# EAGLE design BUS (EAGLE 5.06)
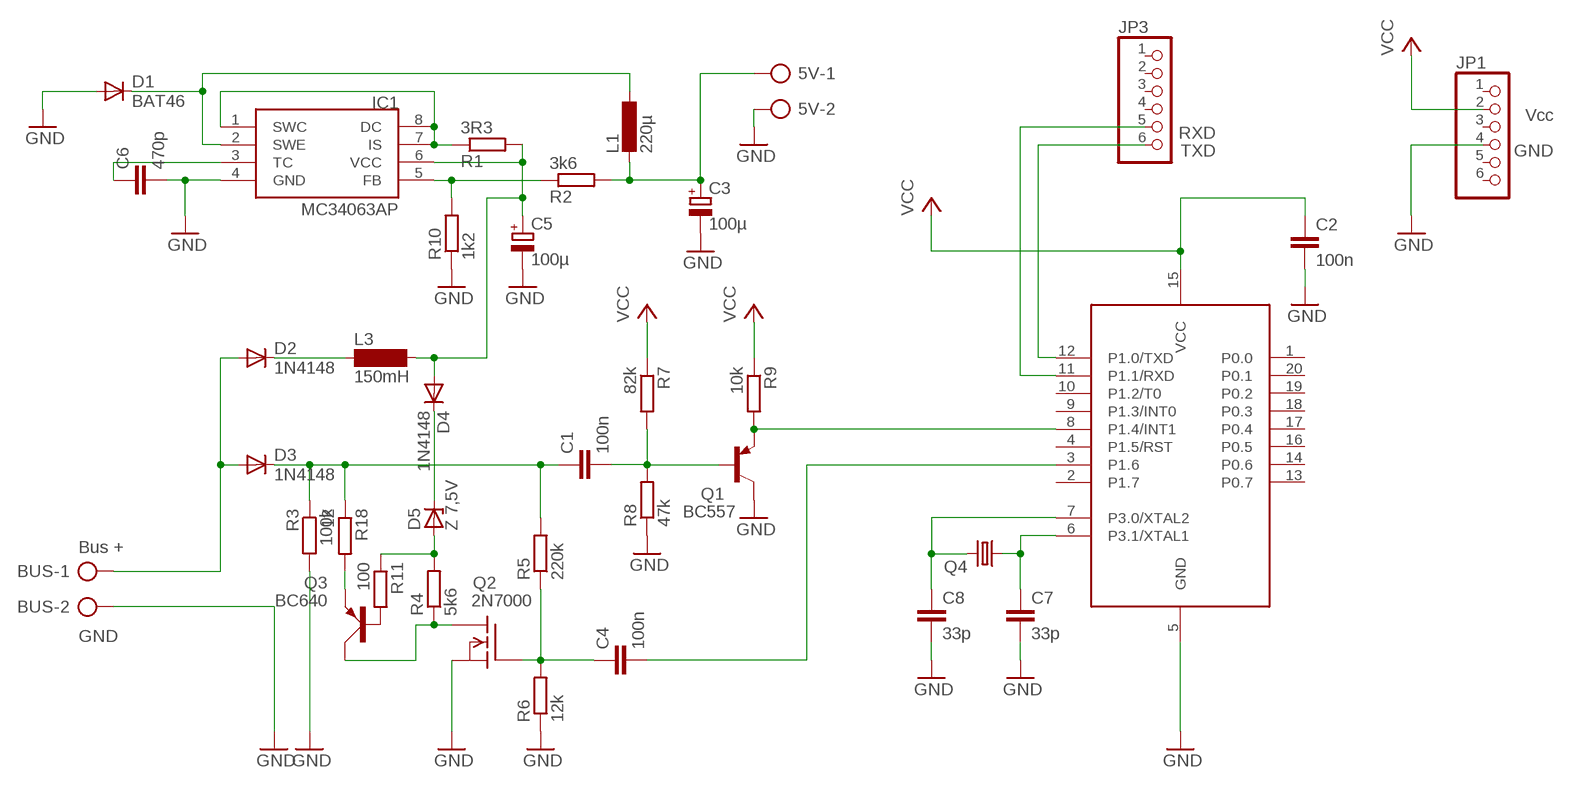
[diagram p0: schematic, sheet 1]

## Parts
5V  AK300/2  [AK300/2]
BUS  AK300/2  [AK300/2]
C1  100n  C-EU050-024X044  [C050-024X044]
C2  100n  C-EU050-024X044  [C050-024X044]
C3  100µ  CPOL-EUE5-8.5  [E5-8,5]
C4  100n  C-EU050-024X044  [C050-024X044]
C5  100µ  CPOL-EUE5-8.5  [E5-8,5]
C6  470p  C-EU025-024X044  [C025-024X044]
C7  33p  C-EU025-024X044  [C025-024X044]
C8  33p  C-EU025-024X044  [C025-024X044]
D1  BAT46  1N4148DO35-7  [DO35-7]
D2  1N4148  1N4148DO35-7  [DO35-7]
D3  1N4148  1N4148DO35-7  [DO35-7]
D4  1N4148  1N4148DO35-7  [DO35-7]
D5  Z 7,5V  ZENER-DIODEZD-7.5  [ZDIO-7.5]
IC1  MC34063AP  [DIL08]
JP1  PINHD-1X6  [1X06]
JP3  PINHD-1X6  [1X06]
L1  220µ  L-EU2200-12.7  [2200-12.7]
L3  150mH  SD12-1000  [SD12_1000]
Q1  BC557  [TO92]
Q2  2N7000  VN2222KM  [TO237]
Q3  BC640  [SOT54D]
Q4  CRYSTALHC49S  [HC49/S]
R1  3R3  R-EU_0207/10  [0207/10]
R2  3k6  R-EU_0207/10  [0207/10]
R3  100k  R-EU_0207/10  [0207/10]
R4  5k6  R-EU_0207/10  [0207/10]
R5  220k  R-EU_0207/10  [0207/10]
R6  12k  R-EU_0207/10  [0207/10]
R7  82k  R-EU_0207/10  [0207/10]
R8  47k  R-EU_0207/10  [0207/10]
R9  10k  R-EU_0207/10  [0207/10]
R10  1k2  R-EU_0207/10  [0207/10]
R11  100  R-EU_0207/10  [0207/10]
R18  12  R-EU_0207/10  [0207/10]
U1  89LPC922  [DIL20]

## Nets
EIB+: BUS.1 D2.A D3.A
GND: 5V.2 BUS.2 C2.2 C3.- C5.- C6.2 C7.2 C8.2 D1.A IC1.4(GND) JP1.4 Q1.3(C) Q2.3(S) R3.2 R6.1 R8.1 R10.1 U1.5(GND)
N$1: Q1.1(E) R9.2 U1.8(P1.4/INT1)
N$2: C1.2 Q1.2(B) R7.2 R8.2
N$3: C8.1 Q4.2 U1.7(P3.0/XTAL2)
N$4: C1.1 D3.C R3.1 R5.2 R18.1
N$5: C4.2 U1.3(P1.6)
N$7: C5.+ D4.A IC1.6(VCC) L3.2 R1.2
N$8: IC1.1(SWC) IC1.7(IS) IC1.8(DC) R1.1
N$9: 5V.1 C3.+ L1.2 R2.2
N$10: JP3.6 U1.12(P1.0/TXD)
N$11: IC1.5(FB) R2.1 R10.2
N$12: D1.C IC1.2(SWE) L1.1
N$13: D2.C L3.1
N$14: C6.1 IC1.3(TC)
N$15: D4.C D5.C
N$16: JP3.5 U1.11(P1.1/RXD)
N$17: C7.1 Q4.1 U1.6(P3.1/XTAL1)
N$25: D5.A R4.2 R11.1
N$26: Q2.1(D) Q3.C R4.1
N$28: Q3.B R11.2
N$33: Q3.E R18.2
N$34: C4.1 Q2.2(G) R5.1 R6.2
VCC: C2.1 JP1.2 R7.1 R9.1 U1.15(VCC)
Unconnected: JP1.1 JP1.3 JP1.5 JP1.6 JP3.1 JP3.2 JP3.3 JP3.4 U1.1(P0.0) U1.2(P1.7) U1.4(P1.5/RST) U1.9(P1.3/INT0) U1.10(P1.2/T0) U1.13(P0.7) U1.14(P0.6) U1.16(P0.5) U1.17(P0.4) U1.18(P0.3) U1.19(P0.2) U1.20(P0.1)

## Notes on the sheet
- Vcc
- RXD
- TXD | GND
- Bus +
- GND

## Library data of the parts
5V BUS = con-ptr500:AK300/2: CONNECTOR
C1 C2 C4 C6-C8 = rcl:C-EU: CAPACITOR, European symbol
C3 C5 = rcl:CPOL-EU: POLARIZED CAPACITOR, European symbol
D1-D4 = diode:1N4148: DIODE
D5 = diode:ZENER-DIODE: Z-Diode
IC1 = mc34063:MC34063
JP1 JP3 = pinhead:PINHD-1X6: PIN HEADER
L1 = rcl:L-EU: INDUCTOR, European symbol
L3 = inductor-neosid:SD12: INDUCTOR
Q1 = transistor-pnp:BC557: PNP Transistor
Q2 = transistor-fet:VN2222KM: N-Channel Enhancement MOSFET (VMOS); 60V; 0,5A; 7,5Ohm
Q3 = transistor-small-signal:BC640: PNP TRANSISTOR
Q4 = crystal:CRYSTAL: CRYSTAL
R1-R11 R18 = resistor:R-EU_: RESISTOR, European symbol
U1 = micro-philips:89LPC922

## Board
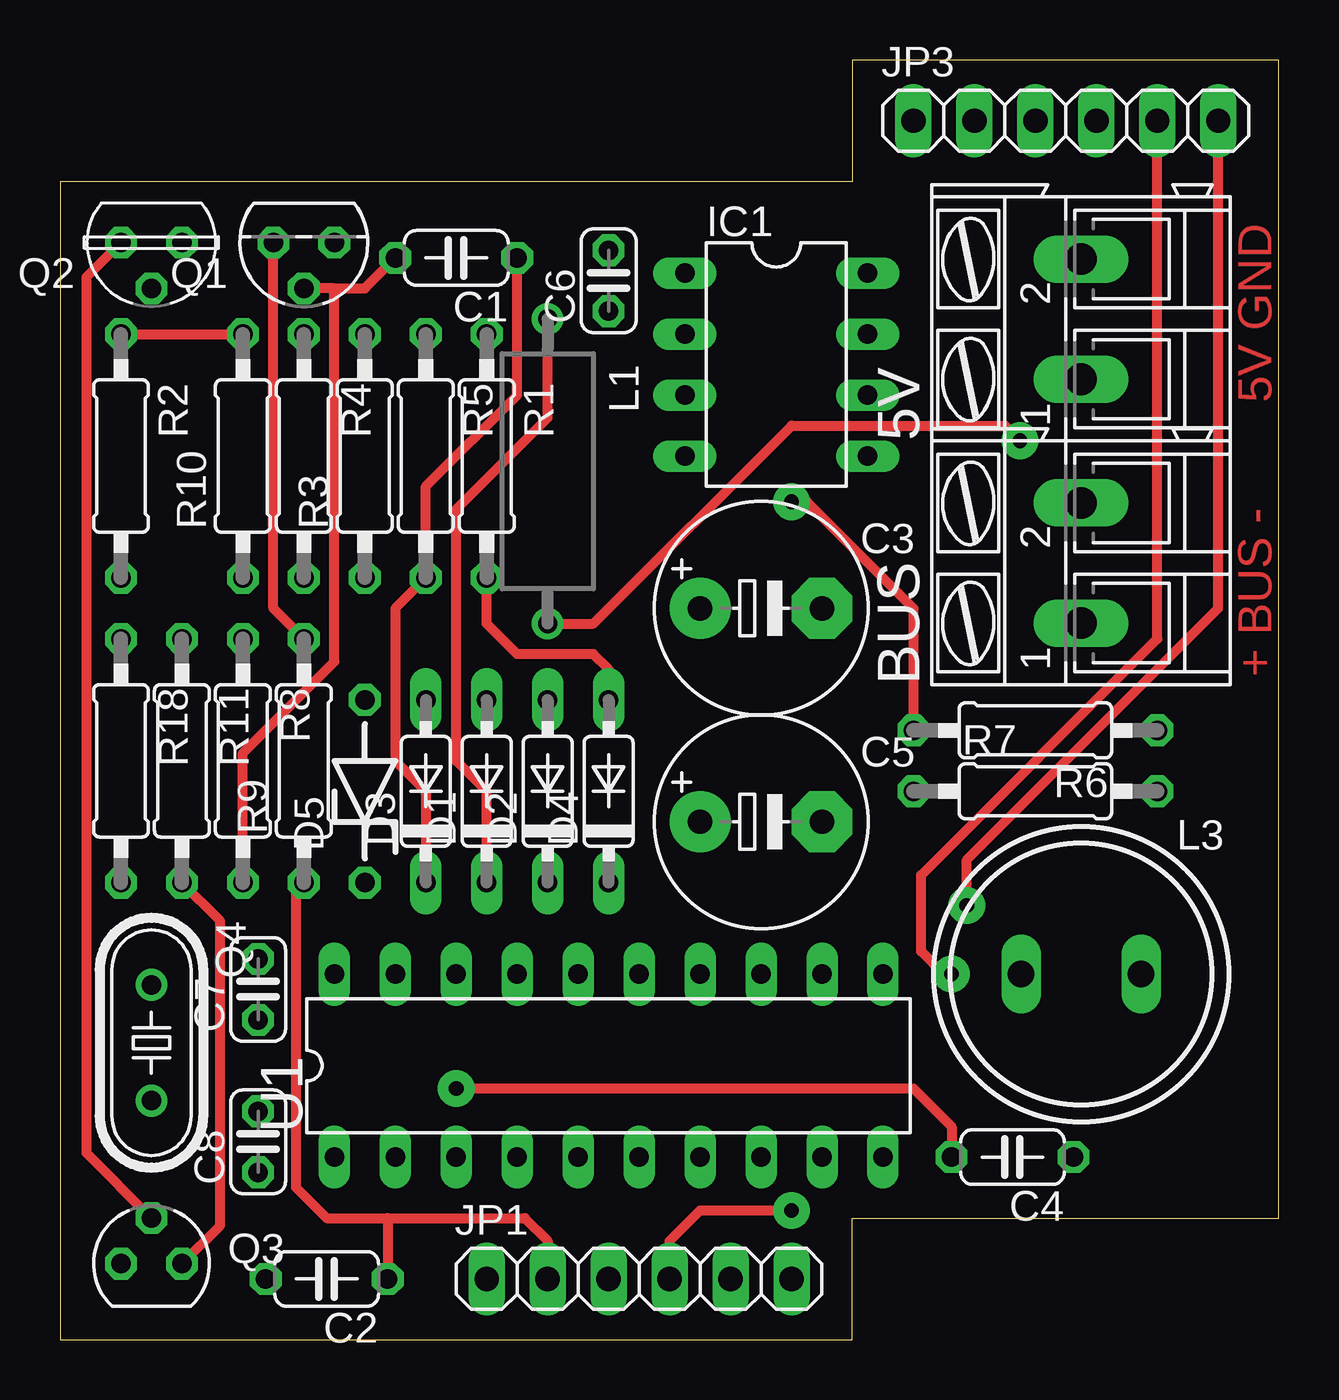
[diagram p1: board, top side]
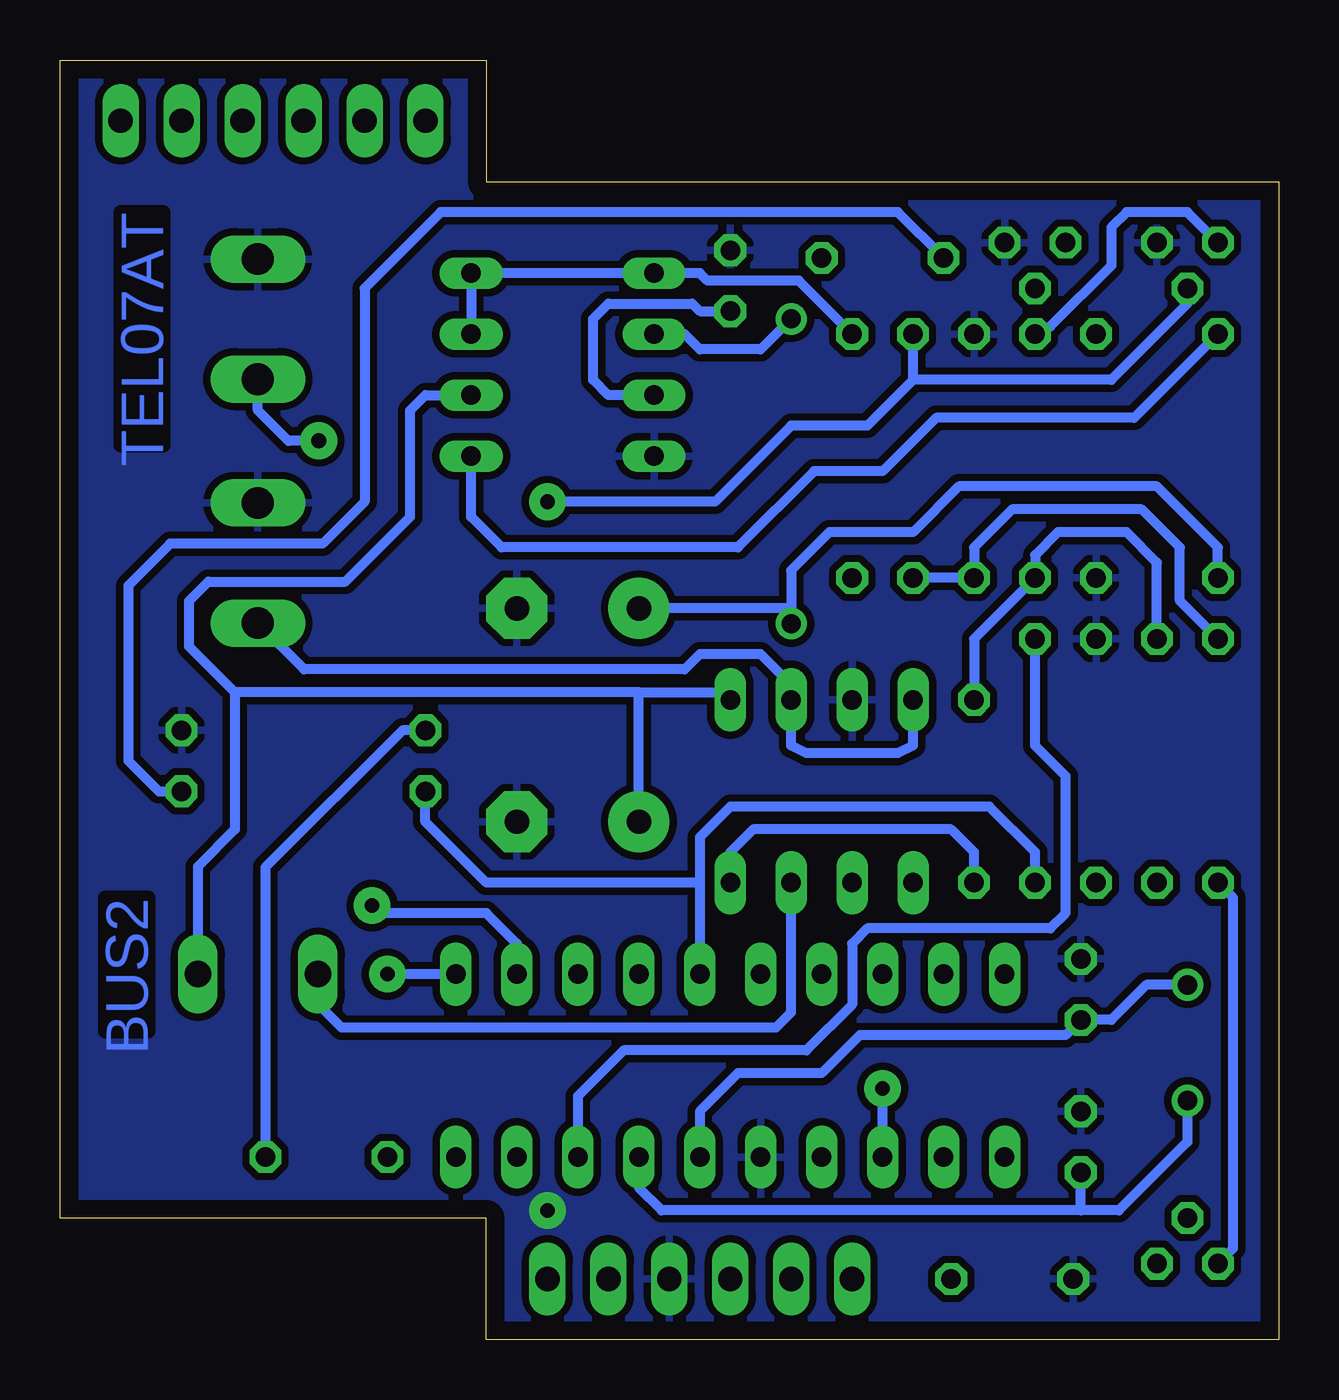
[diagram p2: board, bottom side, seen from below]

Size 50.79 x 53.33 mm. Coordinates in mm from the lower left corner, seen from the top.
Outline: 0,0 33.02,0 33.02,5.08 50.79,5.08 50.79,53.33 33.02,53.33 33.02,48.26 0,48.26 0,0
Copper layers (1*16): Top 0.035mm / dielectric 1.5mm / Bottom 0.035mm
Design rules "default *": minimum track width 12mil, minimum drill 24mil, track to track 8mil, track to pad 8mil, pad to pad 8mil, via to via 8mil, smd to smd 8mil, copper to edge 30mil, drill to drill 8mil, minimum pad ring 10mil, minimum via ring 8mil, stop-mask expansion 4mil, vias tented up to drill 0mil, thermal gap 12mil

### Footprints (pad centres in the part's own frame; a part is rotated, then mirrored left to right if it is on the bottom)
AK300/2 = drill 1.321 long: 1 -2.515,0; 2 2.489,0
C050-024X044 = drill 0.813 octagon: 1 -2.54,0; 2 2.54,0
E5-8,5 = drill 1.016 pad 2.54 round: + -2.54,0 | drill 1.016 pad 2.54 octagon: - 2.54,0
C025-024X044 = drill 0.813 octagon: 1 -1.27,0; 2 1.27,0
DO35-7 = drill 0.813 long: A 3.81,0; C -3.81,0
ZDIO-7.5 = drill 0.813 octagon: A 3.81,0; C -3.81,0
DIL08 = drill 0.813 long: 1 -3.81,-3.81; 2 -1.27,-3.81; 3 1.27,-3.81; 4 3.81,-3.81; 5 3.81,3.81; 6 1.27,3.81; 7 -1.27,3.81; 8 -3.81,3.81
1X06 = drill 1.016 long: 1 -6.35,0; 2 -3.81,0; 3 -1.27,0; 4 1.27,0; 5 3.81,0; 6 6.35,0
2200-12.7 = drill 0.8 pad 1.27 round: 1 -6.35,0; 2 6.35,0
SD12_1000 = drill 1.1 long: 1 -2.5,0; 2 2.5,0
TO92 = drill 0.813 octagon: 1 1.27,0; 2 0,1.905; 3 -1.27,0
TO237 = drill 0.813 octagon: 1 1.27,0; 2 0,1.905; 3 -1.27,0
SOT54D = drill 0.813 octagon: B 1.27,0; C 0,1.905; E -1.27,0
HC49/S = drill 0.813 round: 1 -2.413,0; 2 2.413,0
0207/10 = drill 0.813 octagon: 1 -5.08,0; 2 5.08,0
DIL20 = drill 0.813 long: 1 -11.43,-3.81; 2 -8.89,-3.81; 3 -6.35,-3.81; 4 -3.81,-3.81; 5 -1.27,-3.81; 6 1.27,-3.81; 7 3.81,-3.81; 8 6.35,-3.81; 9 8.89,-3.81; 10 11.43,-3.81; 11 11.43,3.81; 12 8.89,3.81; 13 6.35,3.81; 14 3.81,3.81; 15 1.27,3.81; 16 -1.27,3.81; 17 -3.81,3.81; 18 -6.35,3.81; 19 -8.89,3.81; 20 -11.43,3.81

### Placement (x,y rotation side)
5V  42.54,42.55 90 top
BUS  42.54,32.38 90 top
C1  16.51,45.09 180 top
C2  11.11,2.54 180 top
C3  29.21,30.48 0 top
C4  39.69,7.62 180 top
C5  29.21,21.59 0 top
C6  22.86,44.13 90 top
C7  8.26,14.61 90 top
C8  8.26,8.26 90 top
D1  17.78,22.86 90 top
D2  20.32,22.86 90 top
D3  15.24,22.86 90 top
D4  22.86,22.86 90 top
D5  12.7,22.86 90 top
IC1  29.84,40.64 270 top
JP1  24.13,2.54 0 top
JP3  41.91,50.8 0 top
L1  20.32,36.2 270 top
L3  42.54,15.24 0 top
Q1  10.16,45.72 180 top
Q2  3.81,45.72 180 top
Q3  3.81,3.17 0 top
Q4  3.81,12.38 270 top
R1  17.78,36.83 270 top
R2  2.54,36.83 270 top
R3  12.7,36.83 90 top
R4  10.16,36.83 270 top
R5  15.24,36.83 270 top
R6  40.64,25.4 180 top
R7  40.64,22.86 0 top
R8  7.62,24.13 270 top
R9  10.16,24.13 90 top
R10  7.62,36.83 90 top
R11  5.08,24.13 270 top
R18  2.54,24.13 270 top
U1  22.86,11.43 0 top

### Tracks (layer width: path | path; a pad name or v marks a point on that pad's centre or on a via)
EIB+
  Bottom 0.406: BUS.1 40.61,27.94 24.77,27.94 24.13,28.57 21.59,28.57 20.32,27.3 D2.A 20.32,24.77 19.68,24.45 15.87,24.45 15.24,24.77 D3.A
GND  (via drill 0.61 pad 1.52)
  Top 0.406: JP1.4 25.4,4.13 26.67,5.4 v30.48,5.4
  pour Bottom (isolate 0.305): 0,48.26 0,0 33.02,0 33.02,5.08 50.8,5.08 50.8,53.34 33.02,53.34 33.02,48.26
N$1
  Top 0.406: Q1.1 8.89,30.48 R9.2
  Bottom 0.406: U1.8 29.21,10.16 27.3,12.06 19.68,12.06 17.78,13.97 17.78,16.51 17.14,17.14 9.53,17.14 8.89,17.78 8.89,23.5 10.16,24.77 R9.2
N$2
  Top 0.406: C1.2 12.7,43.81 11.43,43.81 | 11.43,43.81 Q1.2 | R8.2 7.62,24.45 11.43,28.26 11.43,43.81
  Bottom 0.406: R7.2 46.67,22.86 47.94,24.13 47.94,31.43 46.2,33.18 39.85,33.18 38.1,34.92 38.1,43.81 34.92,46.99 15.87,46.99 C1.2
N$3
  Bottom 0.406: U1.7 26.67,6.35 25.72,5.4 8.26,5.4 | 3.81,10.16 Q4.2 3.81,8.26 6.67,5.4 8.26,5.4 | 8.26,5.4 C8.1
N$4
  Top 0.406: C1.1 19.05,39.37 15.24,35.56 R5.2 13.97,30.48 13.97,24.13 15.24,22.86 D3.C
  Bottom 0.406: R18.1 4.13,30.8 4.13,33.02 5.71,34.61 11.11,34.61 12.7,33.02 R3.1 R5.2
N$5  (via drill 0.61 pad 1.52)
  Top 0.406: C4.2 37.15,8.89 35.56,10.48 v16.51,10.48
  Bottom 0.406: U1.3 v16.51,10.48
N$7
  Top 0.406: R1.2 17.78,29.84 19.05,28.57 22.23,28.57 22.86,27.94 D4.A
  Bottom 0.406: IC1.6 35.56,39.37 36.2,38.73 36.2,34.29 38.89,31.59 44.61,31.59 45.4,30.8 45.4,28.89 43.5,26.99 | L3.2 45.04,19.73 43.5,21.27 43.5,26.99 | 26.67,26.99 23.18,26.99 D4.A | 26.67,26.99 43.5,26.99 | C5.+ 26.67,26.99
N$8
  Bottom 0.406: IC1.7 IC1.8 IC1.1 24.13,44.45 23.81,44.13 20,44.13 R1.1
N$9  (via drill 0.61 pad 1.52)
  Top 0.406: L1.2 22.23,29.84 30.48,38.1 39.37,38.1 v40,37.47
  Bottom 0.406: R2.2 2.54,33.02 5.08,35.56 13.33,35.56 15.24,33.66 18.73,33.66 20.32,32.07 20.32,30.48 | 20.32,30.48 L1.2 | v40,37.47 41.27,37.47 42.54,38.73 5V.1 | 20.32,30.48 C3.+
N$10  (via drill 0.61 pad 1.52)
  Top 0.406: v37.78,18.1 37.78,20 48.26,30.48 JP3.6
  Bottom 0.406: U1.12 31.75,16.51 33.02,17.78 37.46,17.78 v37.78,18.1
N$11
  Top 0.406: R2.1 R10.2
  Bottom 0.406: IC1.5 33.66,34.29 32.38,33.02 22.54,33.02 19.37,36.2 16.51,36.2 14.29,38.42 6.03,38.42 R2.1
N$12
  Top 0.406: L1.1 20.32,38.42 16.51,34.61 16.51,24.13 17.78,22.86 D1.C
  Bottom 0.406: IC1.2 24.77,41.91 24.13,41.27 21.59,41.27 L1.1
N$13
  Bottom 0.406: D2.C 20.32,13.65 20.95,13.02 39.05,13.02 40.04,14.01 L3.1
N$14
  Bottom 0.406: IC1.3 27.94,39.37 28.57,40.01 28.57,42.55 27.94,43.18 24.45,43.18 24.13,42.86 C6.1
N$15
  Bottom 0.406: D4.C 22.86,20.32 21.91,21.27 13.65,21.27 12.7,20.32 D5.C
N$16  (via drill 0.61 pad 1.52)
  Top 0.406: JP3.5 45.72,29.21 35.88,19.37 35.88,16.19 36.83,15.24 v37.15,15.24
  Bottom 0.406: U1.11 v37.15,15.24
N$17
  Bottom 0.406: U1.6 24.13,9.53 22.54,11.11 19.05,11.11 17.46,12.7 8.89,12.7 C7.1 6.99,13.34 5.53,14.8 Q4.1
N$25
  Bottom 0.406: R11.1 5.08,32.38 6.35,33.66 9.21,33.66 10.16,32.7 R4.2 12.7,29.21 D5.A
N$26
  Top 0.406: Q3.C 1.11,7.78 1.11,44.29 Q2.1
  Bottom 0.406: Q2.1 3.81,46.99 6.35,46.99 6.99,46.35 6.99,44.77 9.53,42.23 9.84,41.91 R4.1
N$28
  Top 0.406: Q3.B 6.67,4.76 6.67,17.46 R11.2
N$33
  Bottom 0.406: R18.2 1.9,18.41 1.9,3.81 Q3.E
N$34  (via drill 0.61 pad 1.52)
  Top 0.406: v30.48,34.92 31.11,34.92 35.56,30.48 R6.2
  Bottom 0.406: Q2.2 3.81,43.18 6.99,40.01 15.24,40.01 | 15.24,40.01 R5.1 | R6.2 36.51,25.4 42.23,19.68 C4.1 | 15.24,40.01 17.14,38.1 20.32,38.1 23.49,34.92 v30.48,34.92
VCC
  Top 0.406: R9.1 9.84,18.73 9.84,6.35 11.11,5.08 13.65,5.08 | JP1.2 20.32,4.13 19.37,5.08 13.65,5.08 | 13.65,5.08 C2.1
  Bottom 0.406: 24.13,19.05 24.13,20.95 22.86,22.23 12.06,22.23 10.16,20.32 R9.1 | 24.13,19.05 U1.15 | R7.1 35.56,21.59 33.02,19.05 24.13,19.05

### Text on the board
Top: 5V GND | + BUS -
Bottom: TEL07AT | BUS2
